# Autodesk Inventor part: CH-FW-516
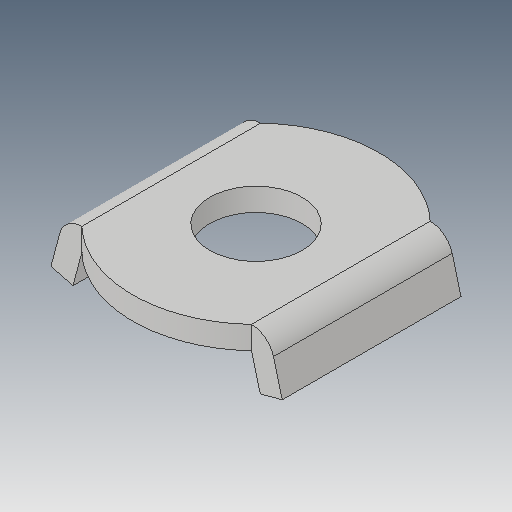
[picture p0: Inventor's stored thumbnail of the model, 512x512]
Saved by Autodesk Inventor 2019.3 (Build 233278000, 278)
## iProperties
Created: 2012-09
Part Number: CH-FW-516
Material: Ogólny
Document SubType Name: Modeling
Designer: CADENGINEERING4
Density: 1 g/cm^3
Appearance: Domyślna
Author: CADENGINEERING4
Revision Number: ÈÎºÎ
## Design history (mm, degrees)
feature "ÇÐ³ý-À­Éì4"
node "Bryła1"
